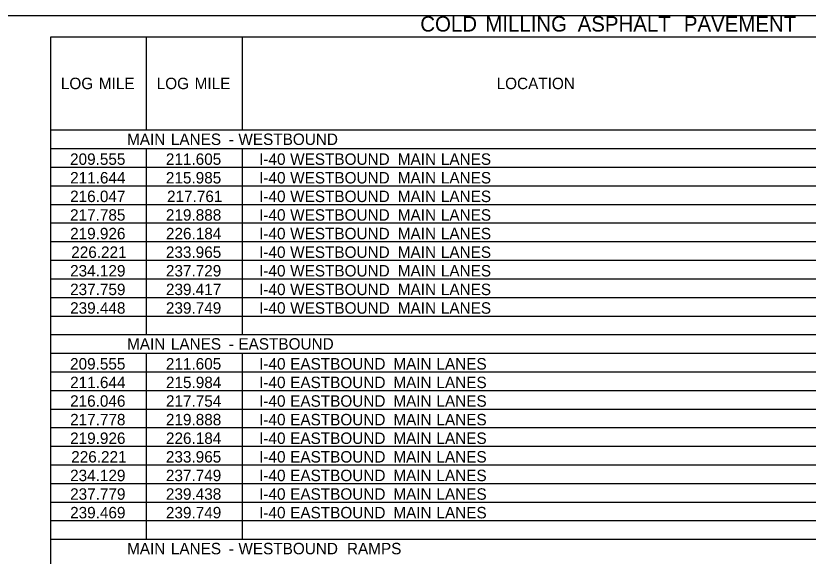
# Model space of a CAD drawing. Extents: x 2261867 to 2275370, y -3124789 to -3122260.
# Drawn here: x 2267326.3 to 2267666.7, y -3124022.5 to -3123790.3 of the extents above; entities that cross this region are included whole.
import ezdxf

# ---------------------------------------------------------------- set-up
doc = ezdxf.new("R2010")
doc.units = 0
doc.layers.add('Default', color=7, linetype='Continuous')
doc.layers.add('DSN_DRFT_Named-Boundary', color=7, linetype='Continuous')

msp = doc.modelspace()

# ---------------------------------------------------------------- linework, layer by layer
at = {"layer": 'Default'}
for p, q in [((2267341.29, -3123799.38), (2267822.99, -3123799.38)), ((2267341.29, -3124734.8), (2267341.29, -3123799.38)), ((2267341.29, -3124734.8), (2267341.29, -3123799.38)), ((2267382.46, -3123839.36), (2267382.46, -3123799.38)), ((2267423.64, -3123839.36), (2267423.64, -3123799.38)), ((2267341.29, -3123839.36), (2267822.99, -3123839.36)), ((2267341.29, -3123847.35), (2267822.99, -3123847.35)), ((2267341.29, -3123847.35), (2267822.99, -3123847.35)), ((2267382.46, -3123927.3), (2267382.46, -3123847.35)), ((2267382.46, -3123927.3), (2267382.46, -3123847.35)), ((2267423.64, -3123927.3), (2267423.64, -3123847.35)), ((2267423.64, -3123927.3), (2267423.64, -3123847.35)), ((2267341.29, -3123855.35), (2267822.99, -3123855.35)), ((2267341.29, -3123863.34), (2267423.64, -3123863.34)), ((2267341.29, -3123863.34), (2267382.46, -3123863.34)), ((2267382.46, -3123863.34), (2267723.45, -3123863.34)), ((2267341.29, -3123871.34), (2267423.64, -3123871.34)), ((2267341.29, -3123871.34), (2267382.46, -3123871.34)), ((2267382.46, -3123871.34), (2267822.99, -3123871.34)), ((2267341.29, -3123879.33), (2267423.64, -3123879.33)), ((2267341.29, -3123879.33), (2267382.46, -3123879.33)), ((2267382.46, -3123879.33), (2267822.99, -3123879.33)), ((2267341.29, -3123887.33), (2267423.64, -3123887.33)), ((2267341.29, -3123887.33), (2267382.46, -3123887.33)), ((2267382.46, -3123887.33), (2267781.81, -3123887.33)), ((2267341.29, -3123895.32), (2267822.99, -3123895.32)), ((2267341.29, -3123903.32), (2267423.64, -3123903.32)), ((2267341.29, -3123903.32), (2267382.46, -3123903.32)), ((2267382.46, -3123903.32), (2267822.99, -3123903.32)), ((2267341.29, -3123911.31), (2267423.64, -3123911.31)), ((2267341.29, -3123911.31), (2267382.46, -3123911.31)), ((2267382.46, -3123911.31), (2267822.99, -3123911.31)), ((2267341.29, -3123919.31), (2267423.64, -3123919.31)), ((2267341.29, -3123919.31), (2267382.46, -3123919.31)), ((2267382.46, -3123919.31), (2267822.99, -3123919.31)), ((2267341.29, -3123927.3), (2267423.64, -3123927.3)), ((2267341.29, -3123927.3), (2267822.99, -3123927.3)), ((2267423.64, -3123927.3), (2267677.48, -3123927.3)), ((2267341.29, -3123935.3), (2267822.99, -3123935.3)), ((2267382.46, -3124015.25), (2267382.46, -3123935.3)), ((2267382.46, -3124015.25), (2267382.46, -3123935.3)), ((2267423.64, -3124015.25), (2267423.64, -3123935.3)), ((2267341.29, -3123943.29), (2267822.99, -3123943.29)), ((2267341.29, -3123951.29), (2267822.99, -3123951.29)), ((2267341.29, -3123959.28), (2267423.64, -3123959.28)), ((2267341.29, -3123959.28), (2267382.46, -3123959.28)), ((2267382.46, -3123959.28), (2267822.99, -3123959.28)), ((2267341.29, -3123967.28), (2267423.64, -3123967.28)), ((2267341.29, -3123967.28), (2267382.46, -3123967.28)), ((2267382.46, -3123967.28), (2267822.99, -3123967.28)), ((2267341.29, -3123975.27), (2267423.64, -3123975.27)), ((2267341.29, -3123975.27), (2267382.46, -3123975.27)), ((2267382.46, -3123975.27), (2267822.99, -3123975.27)), ((2267341.29, -3123983.27), (2267423.64, -3123983.27)), ((2267341.29, -3123983.27), (2267382.46, -3123983.27)), ((2267382.46, -3123983.27), (2267822.99, -3123983.27)), ((2267341.29, -3123991.26), (2267423.64, -3123991.26)), ((2267341.29, -3123991.26), (2267382.46, -3123991.26)), ((2267382.46, -3123991.26), (2267822.99, -3123991.26)), ((2267341.29, -3123999.26), (2267423.64, -3123999.26)), ((2267341.29, -3123999.26), (2267382.46, -3123999.26)), ((2267382.46, -3123999.26), (2267822.99, -3123999.26)), ((2267341.29, -3124007.25), (2267423.64, -3124007.25)), ((2267341.29, -3124007.25), (2267382.46, -3124007.25)), ((2267382.46, -3124007.25), (2267822.99, -3124007.25)), ((2267341.29, -3124015.25), (2267423.64, -3124015.25)), ((2267341.29, -3124015.25), (2267822.99, -3124015.25)), ((2267423.64, -3124015.25), (2267677.48, -3124015.25))]:
    msp.add_line(p, q, dxfattribs=at)
at = {"layer": 'DSN_DRFT_Named-Boundary'}
msp.add_lwpolyline([(2266769.64, -3124789.38), (2268394.64, -3124789.38), (2268394.64, -3123790.32), (2266769.64, -3123790.32)], close=True, dxfattribs=at)

# ---------------------------------------------------------------- texts
at = {"layer": 'Default'}
for s, height, p in [('COLD', 6.56, (2267500.08, -3123797.07)), (' MILLING', 6.56, (2267525.59, -3123797.07)), (' ASPHALT', 6.56, (2267565.26, -3123797.07)), (' PAVEMENT', 6.56, (2267610.9, -3123797.07)), ('LOG', 4.92, (2267345.64, -3123821.83)), (' MILE', 4.92, (2267360.12, -3123821.83)), ('LOG', 4.92, (2267386.82, -3123821.83)), (' MILE', 4.92, (2267401.29, -3123821.83)), ('LOCATION', 4.92, (2267532.88, -3123821.83)), ('MAIN', 4.92, (2267374.07, -3123845.82)), (' LANES', 4.92, (2267391.08, -3123845.82)), (' WESTBOUND', 4.92, (2267420.1, -3123845.82)), (' -', 4.92, (2267415.95, -3123845.82)), ('209.555', 4.92, (2267349.59, -3123854.36)), ('211.605', 4.92, (2267390.77, -3123854.36)), ('I-40', 4.92, (2267430.83, -3123854.36)), (' WESTBOUND', 4.92, (2267442.34, -3123854.36)), (' MAIN', 4.92, (2267488.57, -3123854.36)), (' LANES', 4.92, (2267507.1, -3123854.36)), ('211.644', 4.92, (2267349.62, -3123862.36)), ('215.985', 4.92, (2267390.77, -3123862.36)), ('I-40', 4.92, (2267430.83, -3123862.36)), (' WESTBOUND', 4.92, (2267442.34, -3123862.36)), (' MAIN', 4.92, (2267488.57, -3123862.36)), (' LANES', 4.92, (2267507.1, -3123862.36)), ('216.047', 4.92, (2267349.61, -3123870.35)), ('217.761', 4.92, (2267391.26, -3123870.35)), ('I-40', 4.92, (2267430.83, -3123870.35)), (' WESTBOUND', 4.92, (2267442.34, -3123870.35)), (' MAIN', 4.92, (2267488.57, -3123870.35)), (' LANES', 4.92, (2267507.1, -3123870.35)), ('217.785', 4.92, (2267349.59, -3123878.35)), ('219.888', 4.92, (2267390.78, -3123878.35)), ('I-40', 4.92, (2267430.83, -3123878.35)), (' WESTBOUND', 4.92, (2267442.34, -3123878.35)), (' MAIN', 4.92, (2267488.57, -3123878.35)), (' LANES', 4.92, (2267507.1, -3123878.35)), ('219.926', 4.92, (2267349.61, -3123886.34)), ('226.184', 4.92, (2267390.8, -3123886.34)), ('I-40', 4.92, (2267430.83, -3123886.34)), (' WESTBOUND', 4.92, (2267442.34, -3123886.34)), (' MAIN', 4.92, (2267488.57, -3123886.34)), (' LANES', 4.92, (2267507.1, -3123886.34)), ('226.221', 4.92, (2267350.09, -3123894.34)), ('233.965', 4.92, (2267390.77, -3123894.34)), ('I-40', 4.92, (2267430.83, -3123894.34)), (' WESTBOUND', 4.92, (2267442.34, -3123894.34)), (' MAIN', 4.92, (2267488.57, -3123894.34)), (' LANES', 4.92, (2267507.1, -3123894.34)), ('234.129', 4.92, (2267349.61, -3123902.33)), ('237.729', 4.92, (2267390.78, -3123902.33)), ('I-40', 4.92, (2267430.83, -3123902.33)), (' WESTBOUND', 4.92, (2267442.34, -3123902.33)), (' MAIN', 4.92, (2267488.57, -3123902.33)), (' LANES', 4.92, (2267507.1, -3123902.33)), ('237.759', 4.92, (2267349.61, -3123910.33)), ('239.417', 4.92, (2267390.79, -3123910.33)), ('I-40', 4.92, (2267430.83, -3123910.33)), (' WESTBOUND', 4.92, (2267442.34, -3123910.33)), (' MAIN', 4.92, (2267488.57, -3123910.33)), (' LANES', 4.92, (2267507.1, -3123910.33)), ('239.448', 4.92, (2267349.61, -3123918.32)), ('239.749', 4.92, (2267390.78, -3123918.32)), ('I-40', 4.92, (2267430.83, -3123918.32)), (' WESTBOUND', 4.92, (2267442.34, -3123918.32)), (' MAIN', 4.92, (2267488.57, -3123918.32)), (' LANES', 4.92, (2267507.1, -3123918.32)), ('MAIN', 4.92, (2267374.07, -3123933.76)), (' LANES', 4.92, (2267391.08, -3123933.76)), (' EASTBOUND', 4.92, (2267420.1, -3123933.76)), (' -', 4.92, (2267415.95, -3123933.76)), ('209.555', 4.92, (2267349.59, -3123942.31)), ('211.605', 4.92, (2267390.77, -3123942.31)), ('I-40', 4.92, (2267430.83, -3123942.31)), (' EASTBOUND', 4.92, (2267442.34, -3123942.31)), (' MAIN', 4.92, (2267486.67, -3123942.31)), (' LANES', 4.92, (2267505.2, -3123942.31)), ('211.644', 4.92, (2267349.62, -3123950.3)), ('215.984', 4.92, (2267390.8, -3123950.3)), ('I-40', 4.92, (2267430.83, -3123950.3)), (' EASTBOUND', 4.92, (2267442.34, -3123950.3)), (' MAIN', 4.92, (2267486.67, -3123950.3)), (' LANES', 4.92, (2267505.2, -3123950.3)), ('216.046', 4.92, (2267349.61, -3123958.3)), ('217.754', 4.92, (2267390.8, -3123958.3)), ('I-40', 4.92, (2267430.83, -3123958.3)), (' EASTBOUND', 4.92, (2267442.34, -3123958.3)), (' MAIN', 4.92, (2267486.67, -3123958.3)), (' LANES', 4.92, (2267505.2, -3123958.3)), ('217.778', 4.92, (2267349.61, -3123966.29)), ('219.888', 4.92, (2267390.78, -3123966.29)), ('I-40', 4.92, (2267430.83, -3123966.29)), (' EASTBOUND', 4.92, (2267442.34, -3123966.29)), (' MAIN', 4.92, (2267486.67, -3123966.29)), (' LANES', 4.92, (2267505.2, -3123966.29)), ('219.926', 4.92, (2267349.61, -3123974.29)), ('226.184', 4.92, (2267390.8, -3123974.29)), ('I-40', 4.92, (2267430.83, -3123974.29)), (' EASTBOUND', 4.92, (2267442.34, -3123974.29)), (' MAIN', 4.92, (2267486.67, -3123974.29)), (' LANES', 4.92, (2267505.2, -3123974.29)), ('226.221', 4.92, (2267350.09, -3123982.28)), ('233.965', 4.92, (2267390.77, -3123982.28)), ('I-40', 4.92, (2267430.83, -3123982.28)), (' EASTBOUND', 4.92, (2267442.34, -3123982.28)), (' LANES', 4.92, (2267505.2, -3123982.28)), (' MAIN', 4.92, (2267486.67, -3123982.28)), ('234.129', 4.92, (2267349.61, -3123990.28)), ('237.749', 4.92, (2267390.78, -3123990.28)), ('I-40', 4.92, (2267430.83, -3123990.28)), (' EASTBOUND', 4.92, (2267442.34, -3123990.28)), (' MAIN', 4.92, (2267486.67, -3123990.28)), (' LANES', 4.92, (2267505.2, -3123990.28)), ('237.779', 4.92, (2267349.61, -3123998.27)), ('239.438', 4.92, (2267390.78, -3123998.27)), ('I-40', 4.92, (2267430.83, -3123998.27)), (' EASTBOUND', 4.92, (2267442.34, -3123998.27)), (' MAIN', 4.92, (2267486.67, -3123998.27)), (' LANES', 4.92, (2267505.2, -3123998.27)), ('239.469', 4.92, (2267349.61, -3124006.27)), ('239.749', 4.92, (2267390.78, -3124006.27)), ('I-40', 4.92, (2267430.83, -3124006.27)), (' EASTBOUND', 4.92, (2267442.34, -3124006.27)), (' MAIN', 4.92, (2267486.67, -3124006.27)), (' LANES', 4.92, (2267505.2, -3124006.27)), ('MAIN', 4.92, (2267374.07, -3124021.71)), (' LANES', 4.92, (2267391.08, -3124021.71)), (' WESTBOUND', 4.92, (2267420.1, -3124021.71)), (' RAMPS', 4.92, (2267466.74, -3124021.71)), (' -', 4.92, (2267415.95, -3124021.71))]:
    msp.add_text(s, height=height, dxfattribs=at).set_placement(p)

doc.saveas('drawing.dxf')
